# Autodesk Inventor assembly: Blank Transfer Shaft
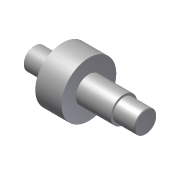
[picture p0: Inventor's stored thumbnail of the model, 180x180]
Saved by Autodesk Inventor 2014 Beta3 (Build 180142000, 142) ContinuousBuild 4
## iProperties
Created: 2011-01
Part Number: Blank Transfer Shaft
Document SubType Name: Assembly
Designer: Beta-8540w
ClientObjectVersion: 1
Author: Beta-8540w
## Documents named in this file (2)
- C:\Inventor 2014 Essentials\Assemblies\Chapter 09\Design Accelerators\Blank Transfer Shaft.iam
- C:\Inventor 2014 Essentials\Assemblies\Chapter 09\Design Accelerators\Blank Transfer Shaft.ipt
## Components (1 placed, 1 different names)
1. Blank Transfer Shaft:1
